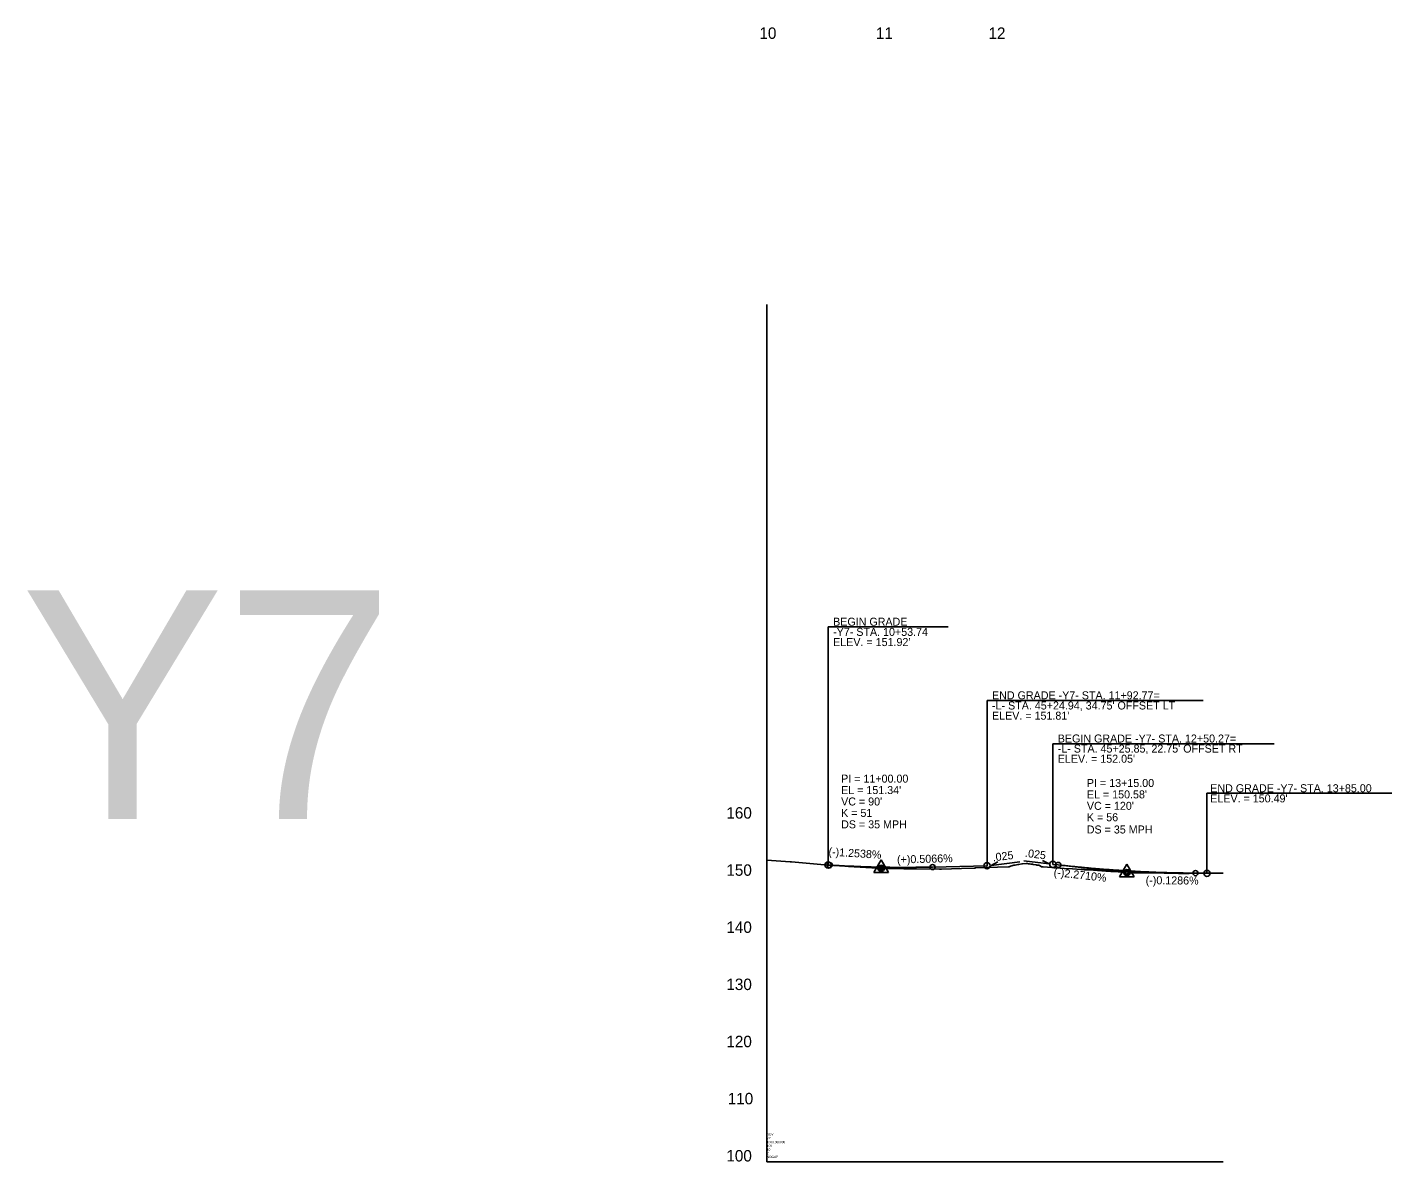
# Model space of a CAD drawing. Extents: x 1778432 to 1784301, y 601022 to 621789.
# Drawn here: x 1779496 to 1780690, y 610039 to 611032 of the extents above; entities that cross this region are included whole.
import ezdxf

# ---------------------------------------------------------------- set-up
doc = ezdxf.new("R2010")
doc.units = 0
for name, color, linetype in [('Exist Profile Cell', 7, 'Continuous'), ('Exist Vertical Profile Ground Line', 7, 'Continuous'), ('Exist Vertical Profile Horizontal Axis Label Major', 7, 'Continuous'), ('Exist Vertical Profile Vertical Axis Label', 7, 'Continuous'), ('Prop PFL Text', 7, 'Continuous'), ('Prop PFL VPI Symbol CELL', 7, 'Continuous'), ('Prop Vertical Profile Curve Label', 7, 'Continuous'), ('Prop Vertical Profile Grade', 7, 'Continuous'), ('Prop Vertical Profile Grade Label', 7, 'Continuous'), ('Prop VPI Label', 7, 'Continuous')]:
    doc.layers.add(name, color=color, linetype=linetype)

msp = doc.modelspace()

# ---------------------------------------------------------------- linework, layer by layer
at = {"layer": 'Exist Profile Cell'}
for q in [(1780143, 610789.2), (1780542.1, 610039.2), (1780143, 610039.2)]:
    msp.add_line((1780143, 610039.2), q, dxfattribs=at)
at = {"layer": 'Exist Vertical Profile Ground Line'}
msp.add_lwpolyline([(1780143, 610303.2), (1780163.4, 610301.6), (1780164.6, 610301.5), (1780190.2, 610299.3), (1780193.2, 610299), (1780211.9, 610297.8), (1780214.6, 610297.6), (1780239.8, 610296.1), (1780244.6, 610295.7), (1780262.9, 610295.5), (1780265.3, 610295.5), (1780294.2, 610295.1), (1780295.3, 610295.1), (1780295.8, 610295.2), (1780313.4, 610295.7), (1780324.4, 610296.1), (1780325, 610296.1), (1780325.5, 610296.2), (1780354.3, 610297.2), (1780355, 610297.2), (1780356.3, 610297.7), (1780357.2, 610298), (1780358.1, 610298.3), (1780359.2, 610298.7), (1780360.4, 610298.8), (1780362.6, 610299.2), (1780363.1, 610299.3), (1780363.5, 610299.4), (1780366.1, 610299.7), (1780366.8, 610299.7), (1780369.8, 610300), (1780370.2, 610300), (1780370.9, 610300), (1780372, 610299.9), (1780372.8, 610299.8), (1780374, 610299.6), (1780375, 610299.5), (1780375.5, 610299.5), (1780375.9, 610299.4), (1780378.7, 610298.9), (1780379.1, 610298.8), (1780380.7, 610298.6), (1780381, 610298.6), (1780382.2, 610298), (1780383.4, 610297.3), (1780384.7, 610297.2), (1780388.6, 610297), (1780392.4, 610296.7), (1780394.2, 610296.4), (1780395.9, 610296.3), (1780403.2, 610295.8), (1780410.5, 610295.4), (1780417.8, 610294.9), (1780420.3, 610294.8), (1780421, 610294.7), (1780421.7, 610294.6), (1780423.7, 610294.6), (1780425.1, 610294.5), (1780432.4, 610294), (1780439.7, 610293.4), (1780441.5, 610293.3), (1780442.4, 610293.3), (1780443.9, 610293.2), (1780446.6, 610293), (1780447, 610293), (1780454.3, 610292.8), (1780461.5, 610292.6), (1780468.8, 610292.4), (1780473.6, 610292.3), (1780475.3, 610292.2), (1780476.1, 610292.2), (1780483.4, 610292), (1780490.7, 610291.8), (1780498, 610291.6), (1780503.2, 610291.5), (1780504.7, 610291.5), (1780505.3, 610291.5), (1780512.6, 610291.5), (1780519, 610291.6), (1780519.9, 610291.6), (1780520.4, 610291.6), (1780527.2, 610291.6), (1780534.5, 610291.7), (1780542.1, 610291.7)], dxfattribs=at)
at = {"layer": 'Prop PFL VPI Symbol CELL'}
for p, q in [((1780243, 610303.4), (1780236.5, 610292.2)), ((1780243, 610303.4), (1780249.5, 610292.2)), ((1780458, 610299.6), (1780451.5, 610288.4)), ((1780458, 610299.6), (1780464.5, 610288.4)), ((1780236.5, 610292.2), (1780249.5, 610292.2)), ((1780451.5, 610288.4), (1780464.5, 610288.4))]:
    msp.add_line(p, q, dxfattribs=at)
for centre, radius in [((1780243, 610295.9), 1.75), ((1780243, 610295.9), 1.2), ((1780458, 610292.1), 1.75), ((1780458, 610292.1), 1.2)]:
    msp.add_circle(centre, radius, dxfattribs=at)
at = {"layer": 'Prop Vertical Profile Curve Label'}
for centre in [(1780198, 610298.7), (1780288, 610297), (1780398, 610298.9), (1780518, 610291.7)]:
    msp.add_circle(centre, 2.25, dxfattribs=at)
at = {"layer": 'Prop Vertical Profile Grade'}
for p, q in [((1780196.7, 610298.8), (1780198, 610298.7)), ((1780288, 610297), (1780335.7, 610298.2)), ((1780393.2, 610299.4), (1780398, 610298.9)), ((1780518, 610291.7), (1780528, 610291.6))]:
    msp.add_line(p, q, dxfattribs=at)
for points in [[(1780198, 610298.7), (1780199.8, 610298.6), (1780201.6, 610298.5), (1780203.4, 610298.4), (1780205.2, 610298.3), (1780207, 610298.2), (1780208.8, 610298.1), (1780210.6, 610298), (1780212.4, 610297.9), (1780214.2, 610297.8), (1780216, 610297.7), (1780217.8, 610297.7), (1780219.6, 610297.6), (1780221.4, 610297.5), (1780223.2, 610297.4), (1780225, 610297.4), (1780226.8, 610297.3), (1780228.6, 610297.2), (1780230.4, 610297.2), (1780232.2, 610297.1), (1780234, 610297.1), (1780235.8, 610297), (1780237.6, 610297), (1780239.4, 610296.9), (1780241.2, 610296.9), (1780243, 610296.9), (1780244.8, 610296.8), (1780246.6, 610296.8), (1780248.4, 610296.8), (1780250.2, 610296.8), (1780252, 610296.7), (1780253.8, 610296.7), (1780255.6, 610296.7), (1780257.4, 610296.7), (1780259.2, 610296.7), (1780261, 610296.7), (1780262.8, 610296.7), (1780264.6, 610296.7), (1780266.4, 610296.7), (1780268.2, 610296.7), (1780270, 610296.7), (1780271.8, 610296.7), (1780273.6, 610296.8), (1780275.4, 610296.8), (1780277.2, 610296.8), (1780279, 610296.8), (1780280.8, 610296.9), (1780282.6, 610296.9), (1780284.4, 610296.9), (1780286.2, 610297), (1780288, 610297)], [(1780398, 610298.9), (1780400.4, 610298.6), (1780402.8, 610298.4), (1780405.2, 610298.1), (1780407.6, 610297.9), (1780410, 610297.6), (1780412.4, 610297.4), (1780414.8, 610297.1), (1780417.2, 610296.9), (1780419.6, 610296.7), (1780422, 610296.4), (1780424.4, 610296.2), (1780426.8, 610296), (1780429.2, 610295.8), (1780431.6, 610295.6), (1780434, 610295.4), (1780436.4, 610295.2), (1780438.8, 610295), (1780441.2, 610294.8), (1780443.6, 610294.7), (1780446, 610294.5), (1780448.4, 610294.3), (1780450.8, 610294.2), (1780453.2, 610294), (1780455.6, 610293.8), (1780458, 610293.7), (1780460.4, 610293.6), (1780462.8, 610293.4), (1780465.2, 610293.3), (1780467.6, 610293.2), (1780470, 610293), (1780472.4, 610292.9), (1780474.8, 610292.8), (1780477.2, 610292.7), (1780479.6, 610292.6), (1780482, 610292.5), (1780484.4, 610292.4), (1780486.8, 610292.3), (1780489.2, 610292.3), (1780491.6, 610292.2), (1780494, 610292.1), (1780496.4, 610292.1), (1780498.8, 610292), (1780501.2, 610291.9), (1780503.6, 610291.9), (1780506, 610291.9), (1780508.4, 610291.8), (1780510.8, 610291.8), (1780513.2, 610291.8), (1780515.6, 610291.7), (1780518, 610291.7)]]:
    msp.add_spline(points, degree=3, dxfattribs=at)
at = {"layer": 'Prop VPI Label'}
for p, q in [((1780196.7, 610298.8), (1780196.7, 610507.1)), ((1780196.7, 610507.1), (1780301.7, 610507.1)), ((1780335.7, 610298.2), (1780335.7, 610442.7)), ((1780335.7, 610442.7), (1780524.6, 610442.7)), ((1780393.2, 610299.4), (1780393.2, 610404.9)), ((1780393.2, 610404.9), (1780586.9, 610404.9)), ((1780528, 610291.6), (1780528, 610361.6)), ((1780528, 610361.6), (1780689.7, 610361.6)), ((1780198, 610298.7), (1780240.2, 610296.1)), ((1780288, 610297), (1780245.7, 610296)), ((1780339.2, 610298.5), (1780345, 610301.7)), ((1780339.2, 610298.5), (1780364.2, 610301.6)), ((1780390, 610299.7), (1780367.9, 610302.4)), ((1780390, 610299.7), (1780384.2, 610302.8)), ((1780398, 610298.9), (1780455.2, 610292.4)), ((1780518, 610291.7), (1780460.7, 610292.1))]:
    msp.add_line(p, q, dxfattribs=at)
for centre in [(1780196.7, 610298.8), (1780243, 610295.9), (1780335.7, 610298.2), (1780393.2, 610299.4), (1780393.2, 610299.4), (1780458, 610292.1), (1780528, 610291.6)]:
    msp.add_circle(centre, 2.75, dxfattribs=at)

# ---------------------------------------------------------------- texts
at = {"layer": 'Exist Profile Cell'}
for s, p in [('Y7', (1780143, 610058.7)), ('RDY', (1780143, 610061.9)), ('1000.000000', (1780143, 610055.4)), ('2', (1780143, 610045.7)), ('100', (1780143, 610052.2)), ('10', (1780143, 610048.9)), ('NOGAP', (1780143, 610042.4))]:
    msp.add_text(s, height=2, dxfattribs=at).set_placement(p)
at = {"layer": 'Exist Vertical Profile Horizontal Axis Label Major'}
for s, p in [('10', (1780136.5, 611021.7)), ('11', (1780238.4, 611021.7)), ('12', (1780336.9, 611021.7))]:
    msp.add_text(s, height=10, dxfattribs=at).set_placement(p)
at = {"layer": 'Exist Vertical Profile Vertical Axis Label'}
for s, p in [('160', (1780107.6, 610339.4)), ('150', (1780107.6, 610289.4)), ('140', (1780107.6, 610239.4)), ('130', (1780107.6, 610189.4)), ('120', (1780107.6, 610139.4)), ('110', (1780108.8, 610089.4)), ('100', (1780107.6, 610039.4))]:
    msp.add_text(s, height=10, dxfattribs=at).set_placement(p)
at = {"layer": 'Prop PFL Text'}
msp.add_text('Y7', height=200, dxfattribs=at).set_placement((1779490.2, 610339.2))
at = {"layer": 'Prop Vertical Profile Curve Label'}
for s, p in [("VC = 90'", (1780208, 610350.9)), ('K = 51', (1780208, 610340.9)), ("VC = 120'", (1780423, 610347.1)), ('K = 56', (1780423, 610337.1)), ('DS = 35 MPH', (1780208, 610330.9)), ('DS = 35 MPH', (1780422.9, 610326.4))]:
    msp.add_text(s, height=7, dxfattribs=at).set_placement(p)
at = {"layer": 'Prop Vertical Profile Grade Label'}
for s, rotation, p in [('(-)1.2538%', 356.406, (1780196.8, 610307.1)), ('(+)0.5066%', 1.4573, (1780257, 610300.1)), ('.025', 7.125, (1780341, 610301.9)), ('.025', 352.875, (1780368.6, 610306)), ('(-)2.2710%', 353.526, (1780393.7, 610289.3)), ('(-)0.1286%', 359.6299, (1780474.4, 610282))]:
    msp.add_text(s, height=7, rotation=rotation, dxfattribs=at).set_placement(p)
at = {"layer": 'Prop VPI Label'}
for s, p in [('BEGIN GRADE', (1780201, 610508.2)), ('-Y7- STA. 10+53.74', (1780201, 610499.3)), ("ELEV. = 151.92'", (1780201, 610490.4)), ("-L- STA. 45+24.94, 34.75' OFFSET LT", (1780340, 610434.9)), ('END GRADE -Y7- STA. 11+92.77=', (1780340, 610443.8)), ("ELEV. = 151.81'", (1780340, 610426)), ("-L- STA. 45+25.85, 22.75' OFFSET RT", (1780397.5, 610397.2)), ('BEGIN GRADE -Y7- STA. 12+50.27=', (1780397.5, 610406)), ("ELEV. = 152.05'", (1780397.5, 610388.3)), ('PI = 11+00.00', (1780208, 610370.9)), ("EL = 151.34'", (1780208, 610360.9)), ('PI = 13+15.00', (1780423, 610367.1)), ('END GRADE -Y7- STA. 13+85.00', (1780530.9, 610362.5)), ("EL = 150.58'", (1780423, 610357.1)), ("ELEV. = 150.49'", (1780530.9, 610353.6))]:
    msp.add_text(s, height=7, dxfattribs=at).set_placement(p)

doc.saveas('drawing.dxf')
